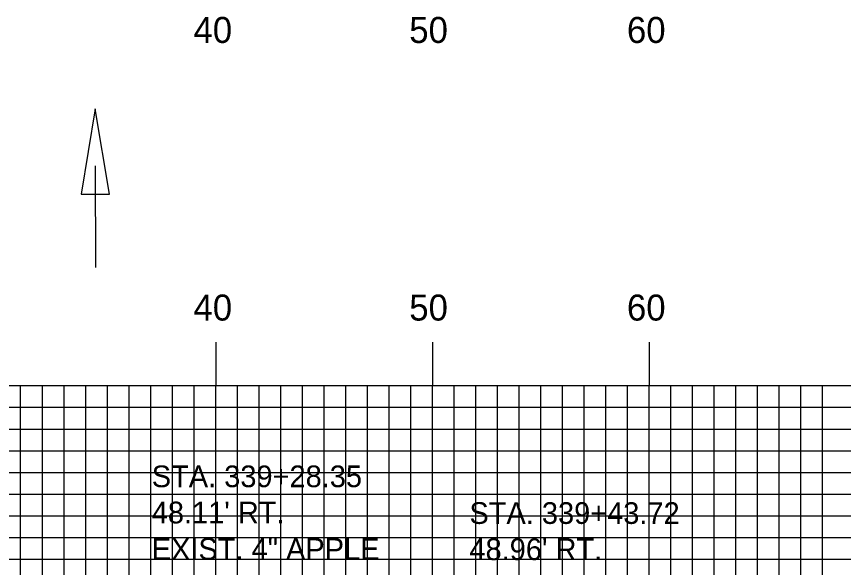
# Model space of a CAD drawing. Extents: x 1824360 to 1824703, y 442591 to 442811.
# Drawn here: x 1824556.14 to 1824594.3, y 442675.28 to 442700.68 of the extents above; entities that cross this region are included whole.
import ezdxf

# ---------------------------------------------------------------- set-up
doc = ezdxf.new("R2010")
doc.units = 0
for name, color, linetype in [('D_Drainage_Ditch_Line', 7, 'Continuous'), ('D_Text_Monospaced', 7, 'Continuous'), ('H_V ANNOTATION', 7, 'Continuous'), ('MAJOR', 7, 'Continuous'), ('MINOR', 7, 'Continuous')]:
    doc.layers.add(name, color=color, linetype=linetype)

msp = doc.modelspace()

# ---------------------------------------------------------------- linework, layer by layer
at = {"layer": 'D_Drainage_Ditch_Line'}
msp.add_line((1824559.78, 442693.805), (1824559.781, 442689.106), dxfattribs=at)
msp.add_lwpolyline([(1824559.124, 442692.492), (1824560.437, 442692.492), (1824559.78, 442696.429)], close=True, dxfattribs=at)
at = {"layer": 'MAJOR'}
for p, q in [((1824565.335, 442685.669), (1824565.335, 442683.665)), ((1824575.335, 442685.669), (1824575.335, 442683.665)), ((1824585.335, 442685.669), (1824585.335, 442683.665)), ((1824385.335, 442683.665), (1824665.335, 442683.665)), ((1824385.335, 442683.665), (1824665.335, 442683.665)), ((1824565.335, 442653.665), (1824565.335, 442683.665)), ((1824575.335, 442653.665), (1824575.335, 442683.665)), ((1824585.335, 442653.665), (1824585.335, 442683.665)), ((1824385.335, 442678.665), (1824665.335, 442678.665))]:
    msp.add_line(p, q, dxfattribs=at)
at = {"layer": 'MINOR'}
for p, q in [((1824556.335, 442653.665), (1824556.335, 442683.665)), ((1824557.335, 442653.665), (1824557.335, 442683.665)), ((1824558.335, 442653.665), (1824558.335, 442683.665)), ((1824559.335, 442653.665), (1824559.335, 442683.665)), ((1824560.335, 442653.665), (1824560.335, 442683.665)), ((1824561.335, 442653.665), (1824561.335, 442683.665)), ((1824562.335, 442653.665), (1824562.335, 442683.665)), ((1824563.335, 442653.665), (1824563.335, 442683.665)), ((1824564.335, 442653.665), (1824564.335, 442683.665)), ((1824566.335, 442653.665), (1824566.335, 442683.665)), ((1824567.335, 442653.665), (1824567.335, 442683.665)), ((1824568.335, 442653.665), (1824568.335, 442683.665)), ((1824569.335, 442653.665), (1824569.335, 442683.665)), ((1824570.335, 442653.665), (1824570.335, 442683.665)), ((1824571.335, 442653.665), (1824571.335, 442683.665)), ((1824572.335, 442653.665), (1824572.335, 442683.665)), ((1824573.335, 442653.665), (1824573.335, 442683.665)), ((1824574.335, 442653.665), (1824574.335, 442683.665)), ((1824576.335, 442653.665), (1824576.335, 442683.665)), ((1824577.335, 442653.665), (1824577.335, 442683.665)), ((1824578.335, 442653.665), (1824578.335, 442683.665)), ((1824579.335, 442653.665), (1824579.335, 442683.665)), ((1824580.335, 442653.665), (1824580.335, 442683.665)), ((1824581.335, 442653.665), (1824581.335, 442683.665)), ((1824582.335, 442653.665), (1824582.335, 442683.665)), ((1824583.335, 442653.665), (1824583.335, 442683.665)), ((1824584.335, 442653.665), (1824584.335, 442683.665)), ((1824586.335, 442653.665), (1824586.335, 442683.665)), ((1824587.335, 442653.665), (1824587.335, 442683.665)), ((1824588.335, 442653.665), (1824588.335, 442683.665)), ((1824589.335, 442653.665), (1824589.335, 442683.665)), ((1824590.335, 442653.665), (1824590.335, 442683.665)), ((1824591.335, 442653.665), (1824591.335, 442683.665)), ((1824592.335, 442653.665), (1824592.335, 442683.665)), ((1824593.335, 442653.665), (1824593.335, 442683.665)), ((1824385.335, 442682.665), (1824665.335, 442682.665)), ((1824385.335, 442681.665), (1824665.335, 442681.665)), ((1824385.335, 442680.665), (1824665.335, 442680.665)), ((1824385.335, 442679.665), (1824665.335, 442679.665)), ((1824385.335, 442677.665), (1824665.335, 442677.665)), ((1824385.335, 442676.665), (1824665.335, 442676.665)), ((1824385.335, 442675.665), (1824665.335, 442675.665))]:
    msp.add_line(p, q, dxfattribs=at)

# ---------------------------------------------------------------- texts
at = {"layer": 'D_Text_Monospaced'}
for s, height, p in [('STA. 339+28.35', 0.99996, (1824562.383, 442678.983)), ("48.11' RT.", 1, (1824562.383, 442677.315)), ('STA. 339+43.72', 0.99996, (1824577.04, 442677.29)), ('EXIST. 4" APPLE', 0.99996, (1824562.383, 442675.635)), ("48.96' RT.", 1, (1824577.04, 442675.622))]:
    msp.add_text(s, height=height, dxfattribs=at).set_placement(p)
at = {"layer": 'H_V ANNOTATION'}
for s, p in [('40', (1824564.307, 442699.465)), ('50', (1824574.264, 442699.465)), ('60', (1824584.307, 442699.465)), ('40', (1824564.307, 442686.665)), ('50', (1824574.264, 442686.665)), ('60', (1824584.307, 442686.665))]:
    msp.add_text(s, height=1.2, dxfattribs=at).set_placement(p)

doc.saveas('drawing.dxf')
